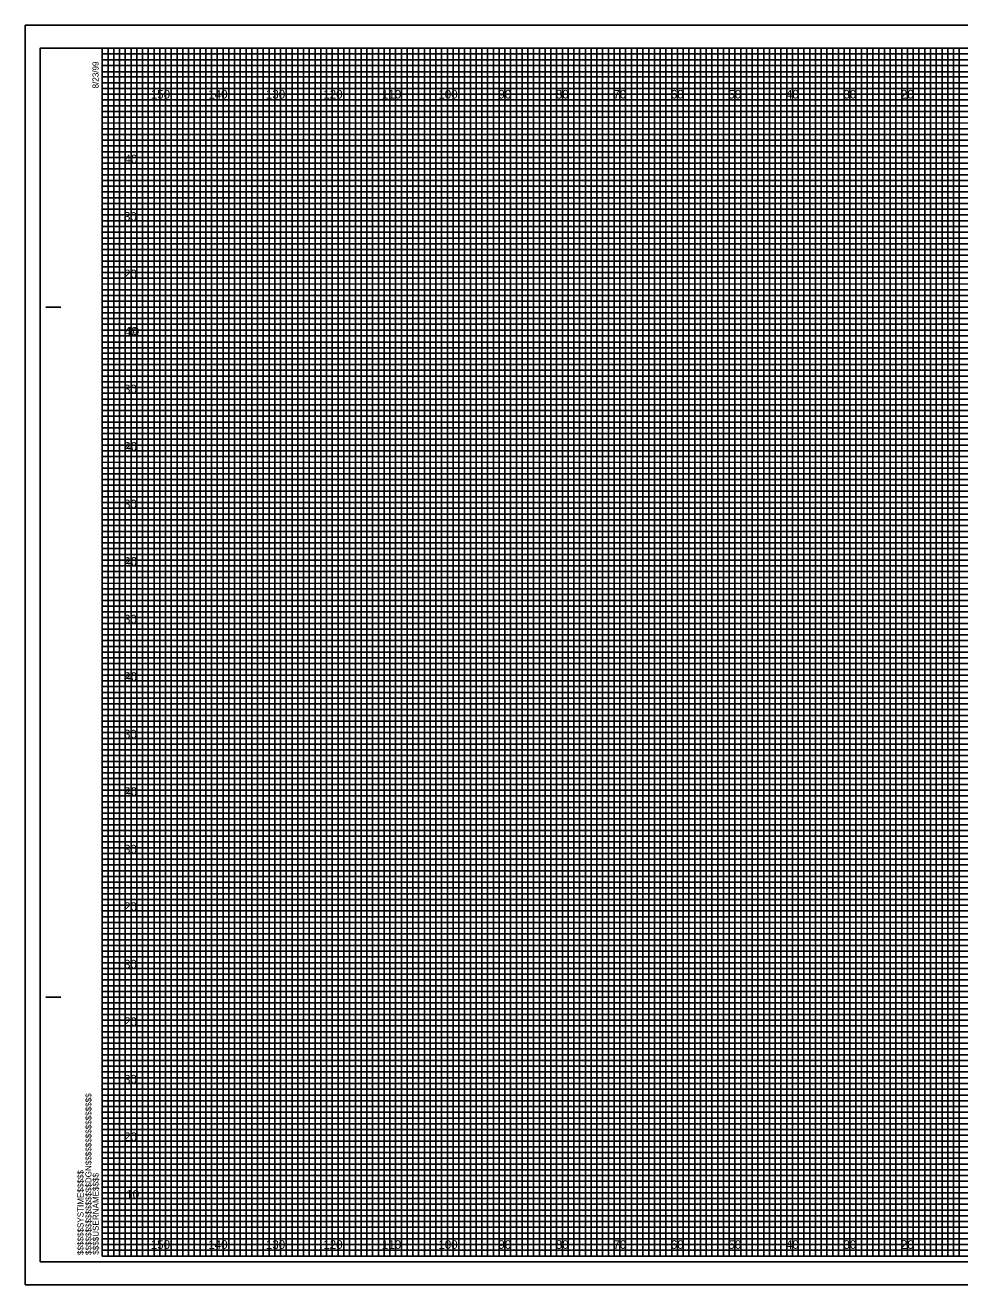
# Model space of a CAD drawing. Extents: x -13 to 323, y -5 to 214.
# Drawn here: x -13.4 to 149.1, y -5 to 214 of the extents above; entities that cross this region are included whole.
import ezdxf

# ---------------------------------------------------------------- set-up
doc = ezdxf.new("R2010")
doc.units = 0
for name, color, linetype in [('Prop XS Elevation Labels', 7, 'Continuous'), ('Prop XS Offset Labels', 7, 'Continuous'), ('Sheet Cross Section CELL', 7, 'Continuous'), ('Sheet Cross Section Grid Major CELL', 7, 'Continuous'), ('Sheet Cross Section Grid Middle CELL', 7, 'Continuous'), ('Sheet Cross Section Grid Minor 1 CELL', 7, 'Continuous'), ('Sheet Cross Section Grid Minor 2 CELL', 7, 'Continuous'), ('Sheet Cutting Line CELL', 7, 'Continuous'), ('Sheet DOT Grid CELL', 7, 'Continuous'), ('Sheet Plot Border Inside CELL', 7, 'Continuous'), ('Sheet Plot Border Outside CELL', 7, 'Continuous')]:
    doc.layers.add(name, color=color, linetype=linetype)

msp = doc.modelspace()

# ---------------------------------------------------------------- linework, layer by layer
at = {"layer": 'Sheet Cross Section CELL'}
for p, q in [((-9.8, 165), (-7.3, 165)), ((-9.7, 165), (-7.2, 165)), ((-9.8, 45), (-7.3, 45)), ((-9.7, 45), (-7.2, 45)), ((0, 0), (0, 0)), ((0, 0), (0, 0)), ((0, 0), (0, 0)), ((0, 0), (0, 0)), ((0, 0), (0, 0)), ((0, 0), (0, 0)), ((0, 0), (0, 0))]:
    msp.add_line(p, q, dxfattribs=at)
msp.add_lwpolyline([(320, 210), (0, 210), (0, 0), (320, 0)], close=True, dxfattribs=at)
at = {"layer": 'Sheet Cross Section Grid Major CELL'}
for p, q in [((10, 210), (0, 210)), ((10, 0), (10, 210)), ((30, 210), (20, 210)), ((20, 210), (20, 0)), ((30, 0), (30, 210)), ((50, 210), (40, 210)), ((40, 210), (40, 0)), ((50, 0), (50, 210)), ((70, 210), (60, 210)), ((60, 210), (60, 0)), ((70, 0), (70, 210)), ((90, 210), (80, 210)), ((80, 210), (80, 0)), ((90, 0), (90, 210)), ((110, 210), (100, 210)), ((100, 210), (100, 0)), ((110, 0), (110, 210)), ((130, 210), (120, 210)), ((120, 210), (120, 0)), ((130, 0), (130, 210)), ((150, 210), (140, 210)), ((140, 210), (140, 0)), ((20, 0), (10, 0)), ((40, 0), (30, 0)), ((60, 0), (50, 0)), ((80, 0), (70, 0)), ((100, 0), (90, 0)), ((120, 0), (110, 0)), ((140, 0), (130, 0))]:
    msp.add_line(p, q, dxfattribs=at)
for points in [[(0, 200), (320, 200), (320, 190), (0, 190)], [(0, 180), (320, 180), (320, 170), (0, 170)], [(0, 160), (320, 160), (320, 150), (0, 150)], [(0, 140), (320, 140), (320, 130), (0, 130)], [(0, 120), (320, 120), (320, 110), (0, 110)], [(0, 100), (320, 100), (320, 90), (0, 90)], [(0, 80), (320, 80), (320, 70), (0, 70)], [(0, 60), (320, 60), (320, 50), (0, 50)], [(0, 40), (320, 40), (320, 30), (0, 30)], [(0, 20), (320, 20), (320, 10), (0, 10)]]:
    msp.add_lwpolyline(points, dxfattribs=at)
at = {"layer": 'Sheet Cross Section Grid Middle CELL'}
for points in [[(0, 210), (5, 210), (5, 0), (15, 0), (15, 210), (25, 210), (25, 0), (35, 0), (35, 210), (45, 210), (45, 0), (55, 0), (55, 210), (65, 210), (65, 0), (75, 0), (75, 210), (85, 210), (85, 0), (95, 0), (95, 210), (105, 210), (105, 0), (115, 0), (115, 210), (125, 210), (125, 0), (135, 0), (135, 210), (145, 210), (145, 0), (155, 0)], [(0, 205), (275, 205)], [(0, 185), (320, 185), (320, 195), (0, 195)], [(0, 165), (320, 165), (320, 175), (0, 175)], [(0, 145), (320, 145), (320, 155), (0, 155)], [(0, 125), (320, 125), (320, 135), (0, 135)], [(0, 105), (320, 105), (320, 115), (0, 115)], [(0, 85), (320, 85), (320, 95), (0, 95)], [(0, 65), (320, 65), (320, 75), (0, 75)], [(0, 45), (320, 45), (320, 55), (0, 55)], [(0, 25), (320, 25), (320, 35), (0, 35)], [(0, 5), (320, 5), (320, 15), (0, 15)]]:
    msp.add_lwpolyline(points, dxfattribs=at)
at = {"layer": 'Sheet Cross Section Grid Minor 1 CELL'}
for p, q in [((0, 209), (260, 209)), ((260, 207.98), (0, 207.98)), ((0, 207.98), (0, 207)), ((0, 207), (260, 207)), ((260, 205.89), (0, 205.89)), ((0, 205.89), (0, 204)), ((0, 204), (320, 204))]:
    msp.add_line(p, q, dxfattribs=at)
for points in [[(0, 203), (270, 203), (320, 203), (320, 202), (0, 202)], [(0, 201), (320, 201), (320, 199), (0, 199)], [(0, 198), (320, 198), (320, 197), (0, 196.98)], [(0, 196), (320, 196), (320, 194), (0, 194)], [(0, 193), (320, 193), (320, 192), (0, 192)], [(0, 191), (320, 191), (320, 189), (0, 189)], [(0, 188), (320, 188), (320, 187), (0, 187)], [(0, 186), (320, 186), (320, 184), (0, 184)], [(0, 183), (320, 183), (320, 182), (0, 182)], [(0, 181), (320, 181), (320, 179), (0, 179)], [(0, 178), (320, 178), (320, 177), (0, 177)], [(0, 176), (320, 176), (320, 173.95), (320, 173), (320, 172), (0, 172)], [(0, 174), (320, 174), (320, 173), (0, 173)], [(0, 171), (320, 171), (320, 169), (0, 169.03)], [(0, 169.03), (320, 169), (320, 168), (0, 168)], [(0, 167), (320, 167), (320, 166), (0, 166)], [(0, 164), (320, 164), (320, 163), (0, 163)], [(0, 162), (320, 162), (320, 161), (0, 161)], [(-0.07, 158.89), (320, 158.89), (320, 157.88), (-0.07, 157.88)], [(0, 157), (320, 157), (320, 156), (0, 156)], [(0, 154), (320, 154), (320, 153), (0, 153)], [(0, 152), (320, 152), (320, 151), (0, 151)], [(0, 149), (320, 149), (320, 148), (0, 148)], [(0, 147), (320, 147), (320, 146), (0, 146)], [(0, 144), (320, 144), (320, 143), (0, 143)], [(0, 142), (320, 142), (320, 141), (0, 141)], [(0, 139), (320, 139), (319.99, 137.98), (0, 138)], [(0, 137), (320, 137), (320, 136), (0, 136)], [(0, 134), (320, 134), (320, 133), (0, 133)], [(0, 132), (320, 132), (320, 131), (0, 131)], [(0, 129), (320, 129), (320, 128), (0, 128)], [(0, 127), (320, 127), (320, 126), (0, 126)], [(0, 124), (320, 124), (320, 123), (0, 123)], [(0, 122), (320, 122), (320, 121), (0, 121)], [(0, 119), (320, 119), (320, 118), (0, 118)], [(0, 116.99), (320.07, 116.91), (320, 116), (0, 116)], [(0, 114), (320, 114), (320, 113), (0, 113)], [(0, 112), (320, 112), (320, 111), (0, 111)], [(0, 109), (320, 109), (320, 108), (0, 108)], [(0, 107), (320, 107), (320, 106), (0, 106)], [(0, 104), (320, 104), (320, 103), (0, 103)], [(0, 102), (320, 102), (320, 101), (0, 101)], [(0, 99), (320, 99), (320, 98), (0, 98)], [(0, 97), (320, 97), (320, 96), (0, 96)], [(0, 94), (320, 94), (320, 93), (0, 93)], [(0, 92), (320, 92), (320, 91), (0, 91)], [(0, 89), (320, 89), (320, 88), (0, 88)], [(0, 87), (320, 87), (320, 86), (0, 86)], [(0, 84), (320, 84), (320, 83), (0, 83)], [(0, 82), (320, 82), (320, 81), (0, 81)], [(0, 79), (320, 79), (319.99, 77.98), (0, 78)], [(0, 77), (320, 77), (320, 76), (0, 76)], [(0, 74), (320, 74), (320, 73), (0, 73)], [(0, 72), (320, 72), (320, 71), (0, 71)], [(0, 69), (320, 69), (320, 68), (0, 68)], [(0, 67), (320, 67), (320, 66), (0, 66)], [(0, 64), (320, 64), (320, 63), (0, 63)], [(0, 62), (320, 62), (320, 61), (0, 61)], [(0, 59), (320, 59), (320, 58), (0, 58)], [(0, 56.99), (320.07, 56.91), (320, 56), (0, 56)], [(0, 54), (320, 54), (320, 53), (0, 53)], [(0, 52), (320, 52), (320, 51), (0, 51)], [(0, 49), (320, 49), (320, 48), (0, 48)], [(0, 47), (320, 47), (320, 46), (0, 46)], [(0, 44), (320, 44), (320, 43), (0, 43)], [(0, 42), (320, 42), (320, 41), (0, 41)], [(0, 39), (320, 39), (320, 38), (0, 38)], [(0, 37), (320, 37), (320, 36), (0, 36)], [(0, 34), (320, 34), (320, 33), (0, 33)], [(0, 32), (320, 32), (320, 31), (0, 31)], [(0, 29), (320, 29), (320, 28), (0, 28)], [(0, 27), (320, 27), (320, 26), (0, 26)], [(0, 24), (320, 24), (320, 23), (0, 23)], [(0, 22), (320, 22), (320, 21), (0, 21)], [(0, 19), (320, 19), (320, 18), (0, 18)], [(0, 17), (320, 17), (320, 16), (0, 16)], [(0, 14), (320, 14), (320, 13), (0, 13)], [(0, 12), (320, 12), (320, 11), (0, 11)], [(0, 9), (320, 9), (320, 8), (0, 8)], [(0, 7), (320, 7), (320, 6), (0, 6)], [(0, 4), (320, 4), (320, 3), (0, 3)], [(0, 2), (320, 2), (320, 1), (0, 1)]]:
    msp.add_lwpolyline(points, dxfattribs=at)
at = {"layer": 'Sheet Cross Section Grid Minor 2 CELL'}
for points in [[(0, 0), (1, 0), (1, 210), (2, 210), (2, 0)], [(2, 0), (3, 0), (3, 210), (4, 210), (4, 0)], [(5, 0), (6, 0), (6, 210), (7, 210), (7, 0)], [(7, 0), (8, 0), (8, 210), (9, 210), (9, 0)], [(10, 0), (11, 0), (11, 210), (12, 210), (12, 0)], [(12, 0), (13, 0), (13, 210), (14, 210), (14, 0)], [(15, 0), (16, 0), (16, 210), (17, 210), (17, 0)], [(17, 0), (18, 0), (18, 210), (19, 210), (19, 0)], [(20, 0), (21, 0), (21, 210), (22, 210), (22, 0)], [(22, 0), (23, 0), (23, 210), (24, 210), (24, 0)], [(25, 0), (26, 0), (26, 210), (27, 210), (27, 0)], [(27, 0), (28, 0), (28, 210), (29, 210), (29, 0)], [(30, 0), (31, 0), (31, 210), (32, 210), (32, 0)], [(32, 0), (33, 0), (33, 210), (34, 210), (34, 0)], [(35, 0), (36, 0), (36, 210), (37, 210), (37, 0)], [(37, 0), (38, 0), (38, 210), (39, 210), (39, 0)], [(40, 0), (41, 0), (41, 210), (42, 210), (42, 0)], [(42, 0), (43, 0), (43, 210), (44, 210), (44, 0)], [(45, 0), (46, 0), (46, 210), (47, 210), (47, 0)], [(47, 0), (48, 0), (48, 210), (49, 210), (49, 0)], [(50, 0), (51, 0), (51, 210), (52, 210), (52, 0)], [(52, 0), (53, 0), (53, 210), (54, 210), (54, 0)], [(55, 0), (56, 0), (56, 210), (57, 210), (57, 0)], [(57, 0), (58, 0), (58, 210), (59, 210), (59, 0)], [(60, 0), (61, 0), (61, 210), (62, 210), (62, 0)], [(62, 0), (63, 0), (63, 210), (64, 210), (64, 0)], [(65, 0), (66, 0), (66, 210), (67, 210), (67, 0)], [(67, 0), (68, 0), (68, 210), (69, 210), (69, 0)], [(70, 0), (71, 0), (71, 210), (72, 210), (72, 0)], [(72, 0), (73, 0), (73, 210), (74, 210), (74, 0)], [(75, 0), (76, 0), (76, 210), (77, 210), (77, 0)], [(77, 0), (78, 0), (78, 210), (79, 210), (79, 0)], [(80, 0), (81, 0), (81, 210), (82, 210), (82, 0)], [(82, 0), (83, 0), (83, 210), (84, 210), (84, 0)], [(85, 0), (86, 0), (86, 210), (87, 210), (87, 0)], [(87, 0), (88, 0), (88, 210), (89, 210), (89, 0)], [(90, 0), (91, 0), (91, 210), (92, 210), (92, 0)], [(92, 0), (93, 0), (93, 210), (94, 210), (94, 0)], [(95, 0), (96, 0), (96, 210), (97, 210), (97, 0)], [(97, 0), (98, 0), (98, 210), (99, 210), (99, 0)], [(100, 0), (101, 0), (101, 210), (102, 210), (102, 0)], [(102, 0), (103, 0), (103, 210), (104, 210), (104, 0)], [(105, 0), (106, 0), (106, 210), (107, 210), (107, 0)], [(107, 0), (108, 0), (108, 210), (109, 210), (109, 0)], [(110, 0), (111, 0), (111, 210), (112, 210), (112, 0)], [(112, 0), (113, 0), (113, 210), (114, 210), (114, 0)], [(115, 0), (116, 0), (116, 210), (117, 210), (117, 0)], [(117, 0), (118, 0), (118, 210), (119, 210), (119, 0)], [(120, 0), (121, 0), (121, 210), (122, 210), (122, 0)], [(122, 0), (123, 0), (123, 210), (124, 210), (124, 0)], [(125, 0), (126, 0), (126, 210), (127, 210), (127, 0)], [(127, 0), (128, 0), (128, 210), (129, 210), (129, 0)], [(130, 0), (131, 0), (131, 210), (132, 210), (132, 0)], [(132, 0), (133, 0), (133, 210), (134, 210), (134, 0)], [(135, 0), (136, 0), (136, 210), (137, 210), (137, 0)], [(137, 0), (138, 0), (138, 210), (139, 210), (139, 0)], [(140, 0), (141, 0), (141, 210), (142, 210), (142, 0)], [(142, 0), (143, 0), (143, 210), (144, 210), (144, 0)], [(145, 0), (146, 0), (146, 210), (147, 210), (147, 0)], [(147, 0), (148, 0), (148, 210), (149, 210), (149, 0)]]:
    msp.add_lwpolyline(points, dxfattribs=at)
at = {"layer": 'Sheet Cutting Line CELL'}
for p, q in [((323.3, 214), (-13.4, 214)), ((-13.4, 214), (-13.4, -5)), ((-13.4, -5), (323.3, -5))]:
    msp.add_line(p, q, dxfattribs=at)
at = {"layer": 'Sheet DOT Grid CELL'}
for p, q in [((10, 0), (10, 210)), ((20, 0), (20, 210)), ((30, 0), (30, 210)), ((40, 0), (40, 210)), ((50, 0), (50, 210)), ((60, 0), (60, 210)), ((70, 0), (70, 210)), ((80, 0), (80, 210)), ((90, 0), (90, 210)), ((100, 0), (100, 210)), ((110, 0), (110, 210)), ((120, 0), (120, 210)), ((130, 0), (130, 210)), ((140, 0), (140, 210)), ((0, 200), (320, 200)), ((0, 190), (320, 190)), ((0, 180), (320, 180)), ((0, 170), (320, 170)), ((0, 160), (320, 160)), ((0, 150), (320, 150)), ((0, 140), (320, 140)), ((0, 130), (320, 130)), ((0, 120), (320, 120)), ((0, 110), (320, 110)), ((0, 100), (320, 100)), ((0, 90), (320, 90)), ((0, 80), (320, 80)), ((0, 70), (320, 70)), ((0, 60), (320, 60)), ((0, 50), (320, 50)), ((0, 40), (320, 40)), ((0, 30), (320, 30)), ((0, 20), (320, 20)), ((0, 10), (320, 10))]:
    msp.add_line(p, q, dxfattribs=at)
at = {"layer": 'Sheet Plot Border Inside CELL'}
msp.add_lwpolyline([(-10.8, -1), (322.4, -1), (322.4, 210), (-10.8, 210)], close=True, dxfattribs=at)
at = {"layer": 'Sheet Plot Border Outside CELL'}
msp.add_lwpolyline([(-13.4, -5), (323.3, -5), (323.3, 214), (-13.4, 214)], close=True, dxfattribs=at)

# ---------------------------------------------------------------- texts
at = {"layer": 'Prop XS Elevation Labels'}
for s, p in [('40', (3.87, 190)), ('30', (3.78, 180)), ('20', (3.8, 170)), ('40', (3.87, 160)), ('10', (4.17, 160)), ('30', (3.78, 150)), ('20', (3.8, 140)), ('40', (3.87, 140)), ('30', (3.78, 130)), ('20', (3.8, 120)), ('40', (3.87, 120)), ('30', (3.78, 110)), ('20', (3.8, 100)), ('40', (3.87, 100)), ('30', (3.78, 90)), ('20', (3.8, 80)), ('40', (3.87, 80)), ('30', (3.78, 70)), ('20', (3.8, 60)), ('30', (3.78, 50)), ('20', (3.8, 40)), ('30', (3.78, 30)), ('20', (3.8, 20)), ('10', (4.17, 10))]:
    msp.add_text(s, height=1.5, dxfattribs=at).set_placement(p)
at = {"layer": 'Prop XS Offset Labels'}
for s, p in [('150', (8.44, 201.25)), ('140', (18.44, 201.25)), ('130', (28.44, 201.25)), ('120', (38.44, 201.25)), ('110', (48.62, 201.25)), ('100', (58.44, 201.25)), ('90', (68.86, 201.25)), ('80', (78.86, 201.25)), ('70', (88.86, 201.25)), ('60', (98.86, 201.25)), ('50', (108.86, 201.25)), ('40', (118.86, 201.25)), ('30', (128.86, 201.25)), ('20', (138.86, 201.25)), ('150', (8.44, 1.25)), ('140', (18.44, 1.25)), ('130', (28.44, 1.25)), ('120', (38.44, 1.25)), ('110', (48.62, 1.25)), ('100', (58.44, 1.25)), ('90', (68.86, 1.25)), ('80', (78.86, 1.25)), ('70', (88.86, 1.25)), ('60', (98.86, 1.25)), ('50', (108.86, 1.25)), ('40', (118.86, 1.25)), ('30', (128.86, 1.25)), ('20', (138.86, 1.25))]:
    msp.add_text(s, height=1.5, dxfattribs=at).set_placement(p)
at = {"layer": 'Sheet Cross Section CELL'}
for s, p in [('8/23/99', (-0.65, 203)), ('$$$$$$$$$$$$$$$$DGN$$$$$$$$$$$$$$$$', (-1.88, 0.18)), ('$$$$$$SYSTIME$$$$$', (-3.26, 0.18)), ('$$$$USERNAME$$$$', (-0.62, 0.23))]:
    msp.add_text(s, height=1.05, rotation=90, dxfattribs=at).set_placement(p)

doc.saveas('drawing.dxf')
